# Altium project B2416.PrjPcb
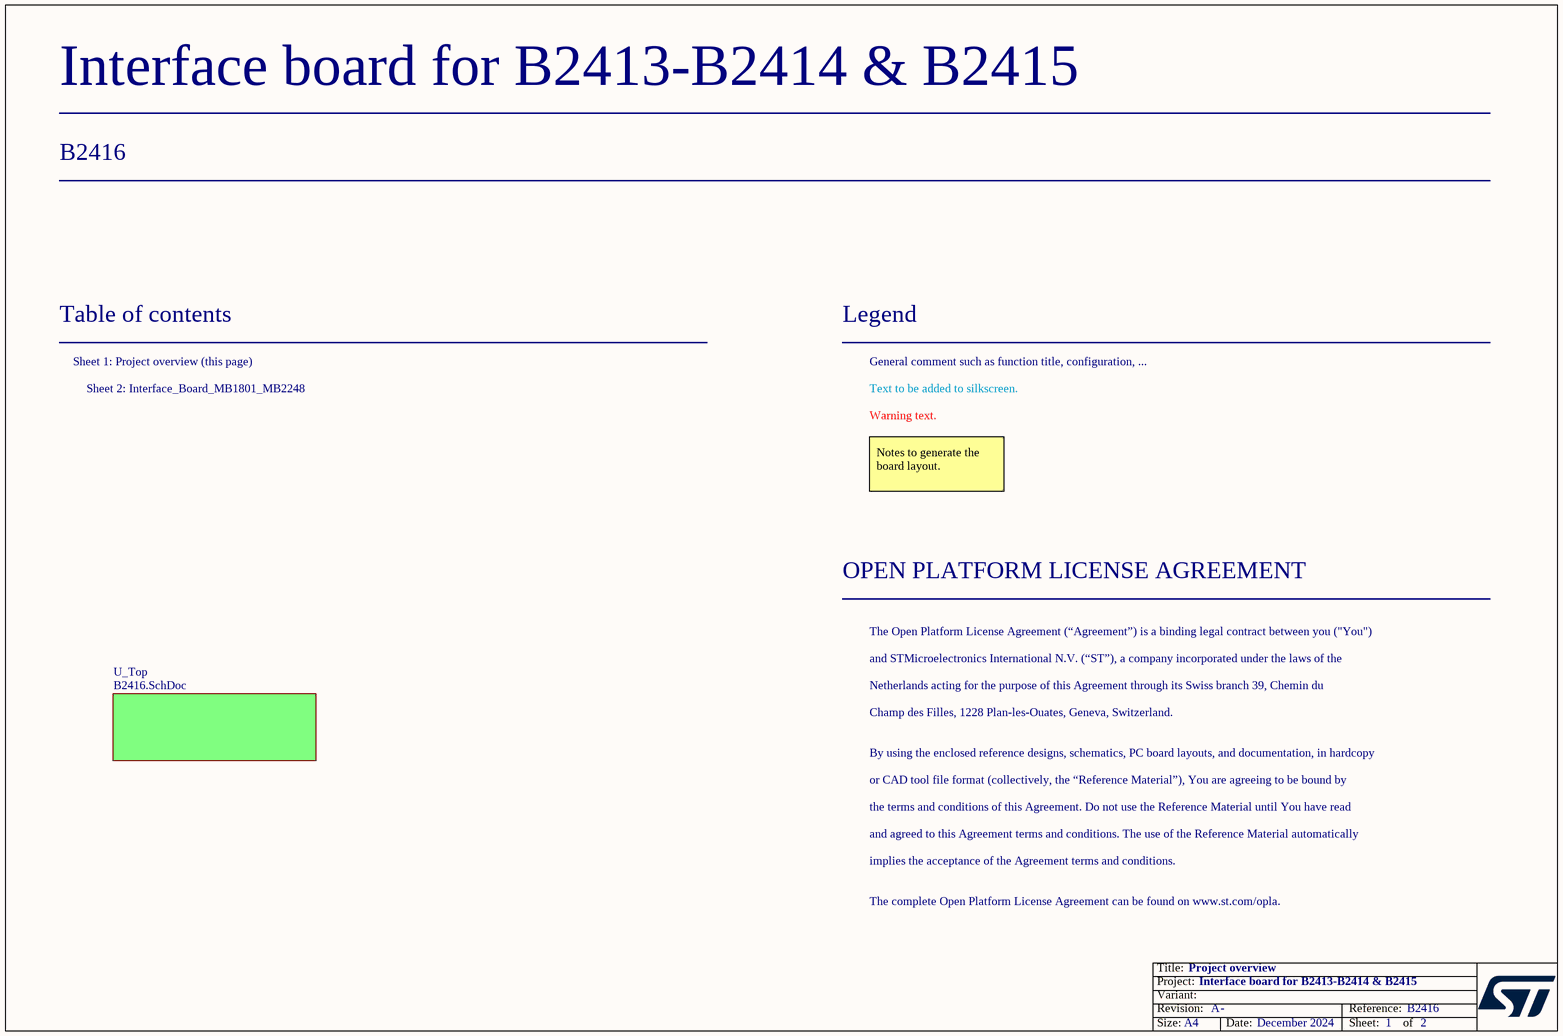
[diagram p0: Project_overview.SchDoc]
Board_Assemble_Revision: 01; Board_Document_Date: December 2024; Board_Name: Interface board for B2413-B2414 & B2415; Board_PCB_Revision: A; Board_Reference: B2416
2 sheets, 56 parts. Net scope: global (net labels, ports and power ports of the same name join across sheets).
Board file: B2416.PcbDoc
Sheets:
  Project_overview.SchDoc
    U_Top = B2416.SchDoc

## Sheet Project_overview.SchDoc: Project overview
size A4; Date: Not used; ApprovedBy: Not used; CheckedBy: Not used; Author: Not used; CompanyName: STMicroelectronics; DrawnBy: Not used; Engineer: Not used; Organization: Not used; Address1: Not used; Address2: Not used; Address3: Not used; Address4: Not used; DocumentNumber: Not used; Revision: Not used; SheetNumber: 1; SheetTotal: 2

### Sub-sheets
U_Top = B2416.SchDoc: no entries

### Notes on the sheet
- Table of contents
- Sheet 1: Project overview (this page)
- Legend
- General comment such as function title, configuration, ...
- Sheet 2: Interface_Board_MB1801_MB2248
- Text to be added to silkscreen.
- Warning text.
- Notes to generate the board layout.
- OPEN PLATFORM LICENSE AGREEMENT
- The Open Platform License Agreement (“Agreement”) is a binding legal contract between you ("You")
- and STMicroelectronics International N.V. (“ST”), a company incorporated under the laws of the
- Netherlands acting for the purpose of this Agreement through its Swiss branch 39, Chemin du
- Champ des Filles, 1228 Plan-les-Ouates, Geneva, Switzerland.
- By using the enclosed reference designs, schematics, PC board layouts, and documentation, in hardcopy
- or CAD tool file format (collectively, the “Reference Material”), You are agreeing to be bound by
- the terms and conditions of this Agreement. Do not use the Reference Material until You have read
- and agreed to this Agreement terms and conditions. The use of the Reference Material automatically
- implies the acceptance of the Agreement terms and conditions.
- The complete Open Platform License Agreement can be found on www.st.com/opla.

## Sheet B2416.SchDoc: Schematic sheet title to update
size A3; Date: Not used; ApprovedBy: Not used; CheckedBy: Not used; Author: Not used; CompanyName: STMicroelectronics; DrawnBy: Not used; Engineer: Not used; Organization: Not used; Address1: Not used; Address2: Not used; Address3: Not used; Address4: Not used; DocumentNumber: Not used; Revision: Not used; SheetNumber: 2; SheetTotal: 2
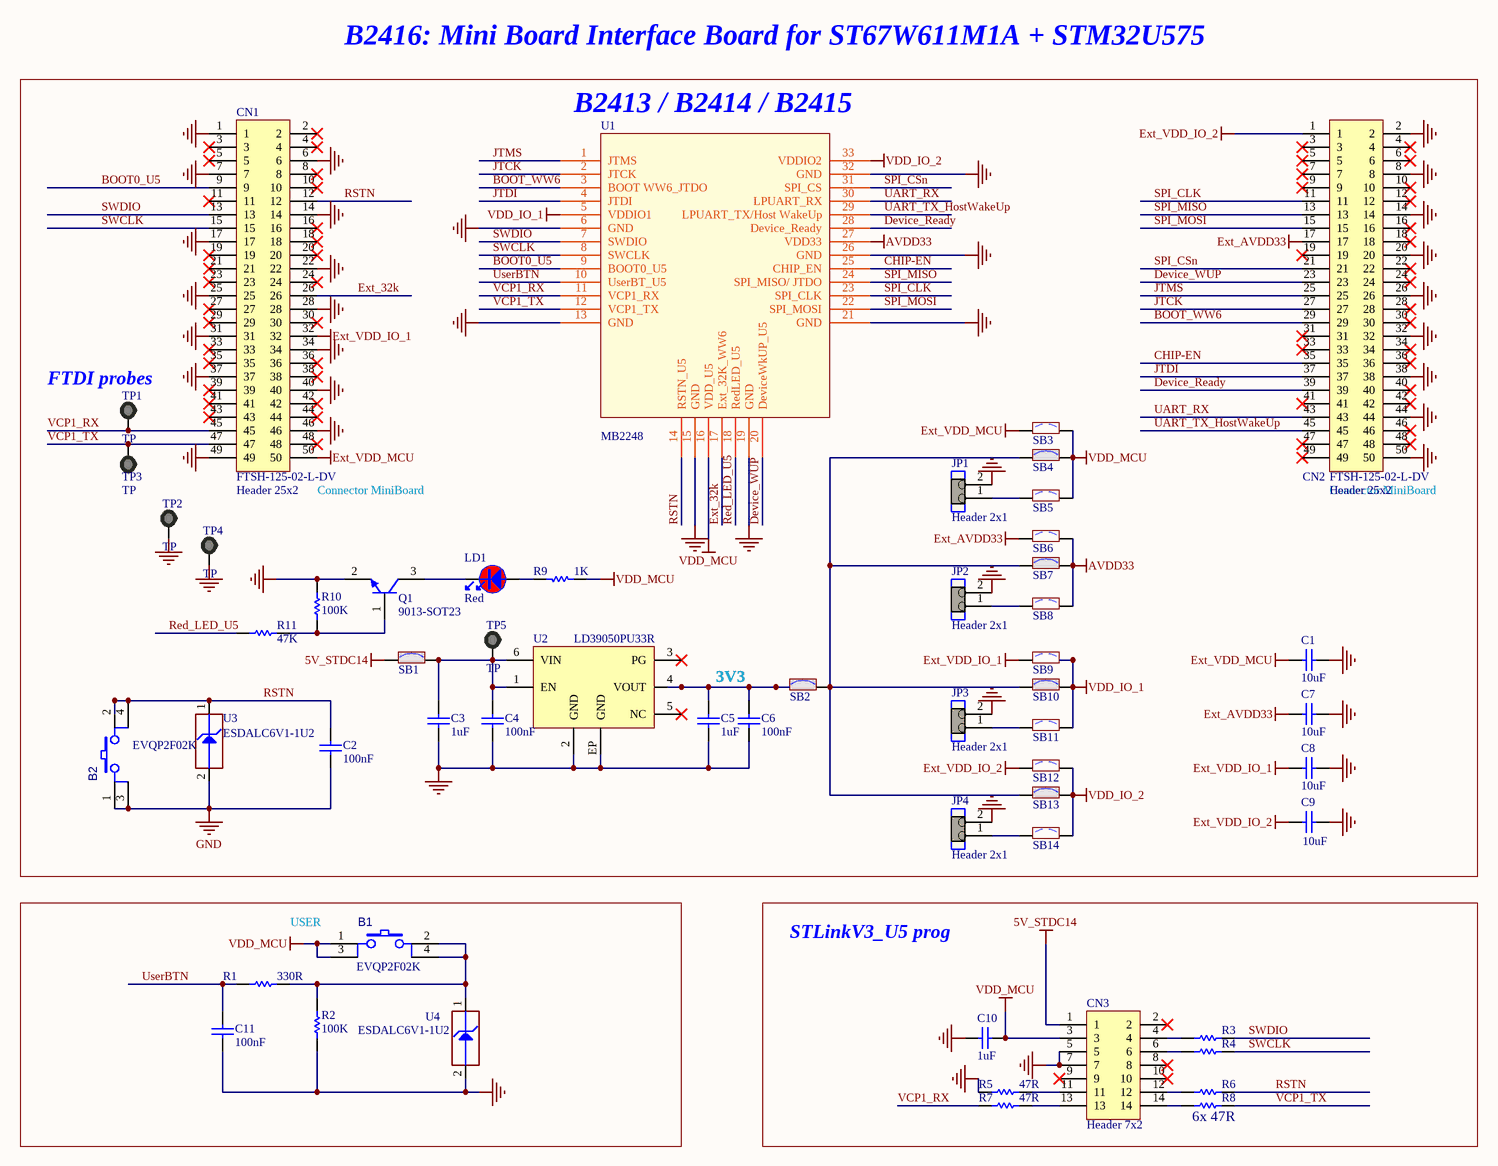
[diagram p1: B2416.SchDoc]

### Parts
B1  value EVQP2F02K  [SWI_PANASONIC_EVQP2F02K]  (hidden comment: SW-PUSH-CMS_EVQP2_BLACK)
B2  value EVQP2F02K  [SWI_PANASONIC_EVQP2F02K]  (hidden comment: SW-PUSH-CMS_EVQP2_BLACK)
C1  value 10uF  [C0402]  (hidden comment: Capacitor)
C2  value 100nF  [C0402]
C3  value 1uF  [C0402]  (hidden comment: Capacitor)
C4  value 100nF  [C0402]  (hidden comment: Capacitor)
C5  value 1uF  [C0402]  (hidden comment: Capacitor)
C6  value 100nF  [C0402]  (hidden comment: Capacitor)
C7  value 10uF  [C0402]  (hidden comment: Capacitor)
C8  value 10uF  [C0402]  (hidden comment: Capacitor)
C9  value 10uF  [C0402]  (hidden comment: Capacitor)
C10  value 1uF  [C0603]  (hidden comment: Capacitor)
C11  value 100nF  [C0402]
CN1  FTSH-125-02-L-DV  value Header 25x2  [CON_SAMTEC_FTSH-125-02-L-DV]
CN2  FTSH-125-02-L-DV  value Header 25x2  [CON_SAMTEC_FTSH-125-02-L-DV]
CN3  Header 7x2  [CON_SAMTEC_FTSH-107-01-L-DV-K-A]
JP1  value Header 2x1  [CON_WP_707-2-02-2-20-00]  (hidden comment: Jumper_Header1.27 2x1 Fitted)
JP2  value Header 2x1  [CON_WP_707-2-02-2-20-00]  (hidden comment: Jumper_Header1.27 2x1 Fitted)
JP3  value Header 2x1  [CON_WP_707-2-02-2-20-00]  (hidden comment: Jumper_Header1.27 2x1 Fitted)
JP4  value Header 2x1  [CON_WP_707-2-02-2-20-00]  (hidden comment: Jumper_Header1.27 2x1 Fitted)
LD1  value Red  [LED_0603_OSRAM_LS-Q976-NR-1_RED_1A2K_H0P8]  (hidden comment: LED_red)
Q1  value 9013-SOT23  [NPN_SOT23]
R1  value 330R  [R0603]
R2  value 100K  [R0603]
R3  Resistor  [R0402]  (value not drawn)
R4  Resistor  [R0402]  (value not drawn)
R5  value 47R  [R0402]  (hidden comment: Resistor)
R6  Resistor  [R0402]  (value not drawn)
R7  value 47R  [R0402]  (hidden comment: Resistor)
R8  Resistor  [R0402]  (value not drawn)
R9  value 1K  [R0603]
R10  value 100K  [R0603]
R11  value 47K  [R0603]
SB1  SB_ON  [SOLDER-BRIDGE_R0402-0R]  (value not drawn)
SB2  SB_ON  [SOLDER-BRIDGE_R0402-0R]  (value not drawn)
SB3  SB_OFF  [SOLDER-BRIDGE_R0402-0R]  (value not drawn)
SB4  SB_ON  [SOLDER-BRIDGE_R0402-0R]  (value not drawn)
SB5  SB_OFF  [SOLDER-BRIDGE_R0402-0R]  (value not drawn)
SB6  SB_OFF  [SOLDER-BRIDGE_R0402-0R]  (value not drawn)
SB7  SB_ON  [SOLDER-BRIDGE_R0402-0R]  (value not drawn)
SB8  SB_OFF  [SOLDER-BRIDGE_R0402-0R]  (value not drawn)
SB9  SB_OFF  [SOLDER-BRIDGE_R0402-0R]  (value not drawn)
SB10  SB_ON  [SOLDER-BRIDGE_R0402-0R]  (value not drawn)
SB11  SB_OFF  [SOLDER-BRIDGE_R0402-0R]  (value not drawn)
SB12  SB_OFF  [SOLDER-BRIDGE_R0402-0R]  (value not drawn)
SB13  SB_ON  [SOLDER-BRIDGE_R0402-0R]  (value not drawn)
SB14  SB_OFF  [SOLDER-BRIDGE_R0402-0R]  (value not drawn)
TP1  value TP  [TP_PTH_1MM_1P4MM]  (hidden comment: Test_Point_PTH_1mm_2mm)  (no BOM)
TP2  value TP  [TP_PTH_1MM_1P4MM]  (hidden comment: Test_Point_PTH_1mm_2mm)  (no BOM)
TP3  value TP  [TP_PTH_1MM_1P4MM]  (hidden comment: Test_Point_PTH_1mm_2mm)  (no BOM)
TP4  value TP  [TP_PTH_1MM_1P4MM]  (hidden comment: Test_Point_PTH_1mm_2mm)  (no BOM)
TP5  value TP  [TP_PTH_1MM_1P4MM]  (hidden comment: Test_Point_PTH_1mm_2mm)  (no BOM)
U1  MB2248  [MB2248_stamp_footprint]
U2  LD39050PU33R  [ICC_DFN6-EPAD_3X3_P095]
U3  value ESDALC6V1-1U2  [ESD_ST0201]  (hidden comment: ESD-TRANSIL)
U4  value ESDALC6V1-1U2  [ESD_ST0201]

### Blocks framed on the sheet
B2413 / B2414 / B2415: B2 C1-C9 CN1 CN2 JP1-JP4 LD1 Q1 R9-R11 SB1-SB14 TP1-TP5 U1-U3
USER: B1 C11 R1 R2 U4
STLinkV3_U5 prog: C10 CN3 R3-R8

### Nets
5V_STDC14: CN3.1 SB1.1
AVDD33: SB6.2 SB7.2 SB8.2 U1.27(VDD33)
Ext_AVDD33: C7.2 CN2.17 SB6.1
Ext_VDD_IO_1: C8.1 CN1.32 SB9.1
Ext_VDD_IO_2: C9.1 CN2.1 SB12.1
Ext_VDD_MCU: C1.2 CN1.50 SB3.1
GND: B2.1 B2.3 C1.1 C2.1 C3.1 C4.1 C5.1 C6.1 C7.1 C8.2 C9.2 C10.1 C11.1 CN1.1 CN1.6 CN1.7 CN1.14 CN1.17 CN1.22 CN1.25 CN1.28 CN1.31 CN1.34 CN1.37 CN1.40 CN1.46 CN1.49 CN2.2 CN2.8 CN2.14 CN2.20 CN2.26 CN2.32 CN2.38 CN2.44 CN2.50 CN3.5 CN3.7 JP1.2 JP2.2 JP3.2 JP4.2 Q1.2(E) R2.1 R5.1 R10.1 TP2.1 TP4.1 U1.6(GND) U1.13(GND) U1.15(GND) U1.19(GND) U1.21(GND) U1.26(GND) U1.32(GND) U2.2(GND) U2.EP(GND) U3.2(GND) U4.2(GND)
VDD_IO_1: SB9.2 SB10.2 SB11.2 U1.5(VDDIO1)
VDD_IO_2: SB12.2 SB13.2 SB14.2 U1.33(VDDIO2)
VDD_MCU: B1.1 B1.3 C10.2 CN3.3 R9.1 SB3.2 SB4.2 SB5.2 U1.16(VDD_U5)
BOOT0_U5: CN1.9 U1.9(BOOT0_U5)
BOOT_WW6: CN2.29 U1.3(BOOT_WW6_JTDO)
CHIP-EN: CN2.35 U1.25(CHIP_EN)
Device_Ready: CN2.39 U1.28(Device_Ready)
Device_WUP: CN2.23 U1.20(DeviceWkUP_U5)
Ext_32k: CN1.26 U1.17(Ext_32K_WW6)
JTCK: CN2.27 U1.2(JTCK)
JTDI: CN2.37 U1.4(JTDI)
JTMS: CN2.25 U1.1(JTMS)
Red_LED_U5: R11.1 U1.18(RedLED_U5)
RSTN: B2.2 B2.4 C2.2 CN1.12 R6.2 U1.14(RSTN_U5) U3.1(IO1)
SPI_CLK: CN2.11 U1.23(SPI_CLK)
SPI_CSn: CN2.21 U1.31(SPI_CS)
SPI_MISO: CN2.13 U1.24(SPI_MISO/_JTDO)
SPI_MOSI: CN2.15 U1.22(SPI_MOSI)
SWCLK: CN1.15 R4.2 U1.8(SWCLK)
SWDIO: CN1.13 R3.2 U1.7(SWDIO)
UART_RX: CN2.43 U1.30(LPUART_RX)
UART_TX_HostWakeUp: CN2.45 U1.29(LPUART_TX/Host_WakeUp)
UserBTN: C11.2 R1.1 U1.10(UserBT_U5)
VCP1_RX: CN1.45 R7.1 TP1.1 U1.11(VCP1_RX)
VCP1_TX: CN1.47 R8.2 TP3.1 U1.12(VCP1_TX)
NetB1_2: B1.2 B1.4 R1.2 R2.2 U4.1(IO1)
NetC3_2: C3.2 C4.2 SB1.2 TP5.1 U2.1(EN) U2.6(VIN)
NetC5_2: C5.2 C6.2 SB2.1 U2.4(VOUT)
NetCN3_4: CN3.4 R3.1
NetCN3_6: CN3.6 R4.1
NetCN3_11: CN3.11 R5.2
NetCN3_12: CN3.12 R6.1
NetCN3_13: CN3.13 R7.2
NetCN3_14: CN3.14 R8.1
NetJP1_1: JP1.1 SB5.1
NetJP2_1: JP2.1 SB8.1
NetJP3_1: JP3.1 SB11.1
NetJP4_1: JP4.1 SB14.1
NetLD1_1: LD1.1 R9.2
NetLD1_2: LD1.2 Q1.3(C)
NetQ1_1: Q1.1(B) R10.2 R11.2
NetSB2_2: SB2.2 SB4.1 SB7.1 SB10.1 SB13.1

Not connected (* = marked no-connect by the designer): CN1 2* 3* 4* 5* 8* 10* 11* 16* 18* 19* 20* 21* 23* 24* 27* 29* 30* 33* 35* 36* 38* 39* 41* 42* 43* 44* 48*; CN2 3* 4* 5* 6* 7* 9* 10* 12* 16* 18* 19* 22* 24* 28* 30* 31* 33* 34* 36* 40* 41* 42* 46* 47* 48* 49*; CN3 2* 8* 9* 10*; U2 3(PG)* 5(NC)*

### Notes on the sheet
- B2416: Mini Board Interface Board for ST67W611M1A + STM32U575
- (near TP1) FTDI probes
- (near CN1) Connector MiniBoard
- (near CN2) Connector MiniBoard
- 3V3
- (near R8) 6x 47R

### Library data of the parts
B1 B2 = MCD-00168: EVQP2 - 4.7mm x 3.5 mm SMD Light Touch Switch; Part_Type: Misc; Part_Preference: Recommended; Manufacturer: PANASONIC; Component_Country_Of_Origin: Japan; ShowFields: YES; ID: 2700
C1 C7-C9 = MCD-01532: Capacitor, MLCC, 10uF, 10V, X5R, +/-20%, 0402, T=0.5mm; Part_Preference: Recommended; Manufacturer: MURATA; Manufacturer_Part_Number: GRM155R61A106ME11; Component_Country_Of_Origin: Japan; ShowFields: YES; ID: 3632
C2 C11 = MCD-00006: Capacitor, MLCC, 100nF, 16V, X7R, 10%, 0402, T=0.5mm; Manufacturer_Part_Number: CC0402KRX7R7BB104; Manufacturer: YAGEO; Alternate_Manufacturer_Part_Number: GCM155R71C104KA55D; Alternate_Manufacturer: MURATA; Provided_By: SUBCO; ECCN_US: EAR99; ECCN_EU: NEC
C3 C5 = MCD-03432: Capacitor, MLCC, 1uF, 6.3V, X5R, +/- 10%, 0402, T=0.5mm; Part_Preference: Recommended; Manufacturer: MURATA; Manufacturer_Part_Number: GRM155R70J105KA12; Order_Code_RS: 113-8711; Component_Country_Of_Origin: China, Japan, Philippines, Singapore; ShowFields: YES; ID: 5548
C4 C6 = MCD-00102: Capacitor, MLCC, 100nF, 16V, X7R, +/-10%, 0402, T=0.5mm; Part_Preference: Not recommended; Manufacturer: YAGEO; Manufacturer_Part_Number: CC0402KRX7R7BB104; Order_Code_RS: 616-9701; Component_Country_Of_Origin: China; ShowFields: YES; ID: 2771
C10 = MCD-00010: Capacitor, MLCC, 1uF, 16V, X5R, 10%, 0603, T=0,8mm; Manufacturer_Part_Number: CC0603KRX5R7BB105; Manufacturer: YAGEO; Provided_By: Subcon; Initial_Board_Reference: MB1274
CN1 CN2 = MCD-02746: Header, 25x2, 12.7mm, VR, SMD, T=4.83mm; Part_Type: Connector; Part_Preference: Recommended; Manufacturer: SAMTEC; Component_Country_Of_Origin: China, Costa Rica, Malaysia, USA, Vietnam; ShowFields: YES; ID: 4858
CN3 = MCD-01531: Header, 7x2, 1.27mm, VR, T=5.97mm, FTSH series STDC14 without Alignment Pin; Part_Type: Connector; Part_Preference: Recommended; Manufacturer: SAMTEC; Manufacturer_Part_Number: FTSH-107-01-L-DV-K; Order_Code_RS: 179-9021; Component_Country_Of_Origin: China, Costa Rica, Malaysia, United States, Vietnam
JP1-JP4 = MCD-01428: Header, 2x1, 1.27mm, RA, TH, T=3.05mm/2.29mm; Part_Type: Connector; Part_Preference: Recommended; Manufacturer: W&P PRODUCTS; Manufacturer_Part_Number: 707-2-02-2-20-00; Component_Country_Of_Origin: China; ShowFields: YES; ID: 3528
LD1 = MCD-00586: LED, Red, 2V, 20mA, 0603; Part_Type: Display; Part_Preference: Recommended; Manufacturer: OSRAM OPTO SEMICONDUCTORS; Manufacturer_Part_Number: LS Q976-NR-1; Partial_Alternate_Internal_Part_Number: MCD-02787; Order_Code_RS: 121-7784; Component_Country_Of_Origin: Unknown; ShowFields: YES; ID: 3158
Q1 = MCD-00073: NPN Bipolar Transistor; Part_Type: IC; Manufacturer_Part_Number: BSR14; Manufacturer: NXP; ECCN_US: EAR99; ECCN_EU: NEC; Provided_By: Subcon; Initial_Board_Reference: MB1274
R1 = MCD-00197: Resistor,330R,0603,1%,1/10W; Manufacturer_Part_Number: RC0603FR-07330RL; Manufacturer: YAGEO; Provided_By: Subcon
R2 R10 = MCD-00223: Resistor,100K,0603,1%,1/10W; Manufacturer_Part_Number: RC0603FR-07100KL; Manufacturer: YAGEO; Provided_By: Subcon; Initial_Board_Reference: MB1319
R3-R8 = MCD-00481: Resistor,47R,0402,1%,1/16W; Manufacturer_Part_Number: RC0402FR-0747RL; Manufacturer: YAGEO; Provided_By: Subcon
R9 = MCD-00070: Resistor,1K,0603,1%,1/10W; Manufacturer_Part_Number: RC0603FR-071KL; Manufacturer: YAGEO; Provided_By: Subcon; Initial_Board_Reference: MB1274
R11 = MCD-00222: Resistor,47K,0603,1%,1/10W; Manufacturer_Part_Number: RC0603FR-0747KL; Manufacturer: YAGEO; Provided_By: Subcon; Initial_Board_Reference: MB1319
SB1 SB2 SB4 SB7 SB10 SB13 = MCD-01618: Resistor, 0R, SB0402, 5%, 0.063W; Manufacturer_Part_Number: RC0402JR-070RL; Manufacturer: YAGEO; Part_Preference: Recommended; ShowFields: YES; ID: 3718; Order_Code_RS: 618-5804; Component_Country_Of_Origin: China
SB3 SB5 SB6 SB8 SB9 SB11 SB12 SB14 = MCD-02162: Solder Bridge 0402 OFF; Part_Type: Misc; Part_Preference: Recommended; Manufacturer: YAGEO; Manufacturer_Part_Number: RC0402JR-070RL; Order_Code_RS: 618-5804; Component_Country_Of_Origin: China
TP1-TP5 = MCD-03401: Test Point trought hole 1mm/1.4mm; Part_Type: Misc; Part_Preference: Recommended; Component_Country_Of_Origin: Unknown; ShowFields: YES; ID: 5517
U2 = MCD-00215: Low quiescent current and low noise voltage regulators; Manufacturer: STMICROELECTRONICS; Part_Type: IC; BMS_Part_Number: 9176126; Part_Preference: Recommended; Manufacturer_HQ_COO: EU; Component_Country_Of_Origin: Malaysia; ShowFields: YES; ID: 2654
U3 = MCD-00170: ESD protection 6V1; BMS_Part_Number: 9151132; Part_Type: Diode; Part_Preference: Recommended; Manufacturer: STMICROELECTRONICS; Manufacturer_HQ_COO: EU; Component_Country_Of_Origin: China; ShowFields: YES; ID: 2696
U4 = MCD-00170: ESD protection 6V1; Part_Type: Diode; Manufacturer: STMICROELECTRONICS; ECCN_US: EAR99; ECCN_EU: NEC; Provided_By: Subcon; Initial_Board_Reference: MB1274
